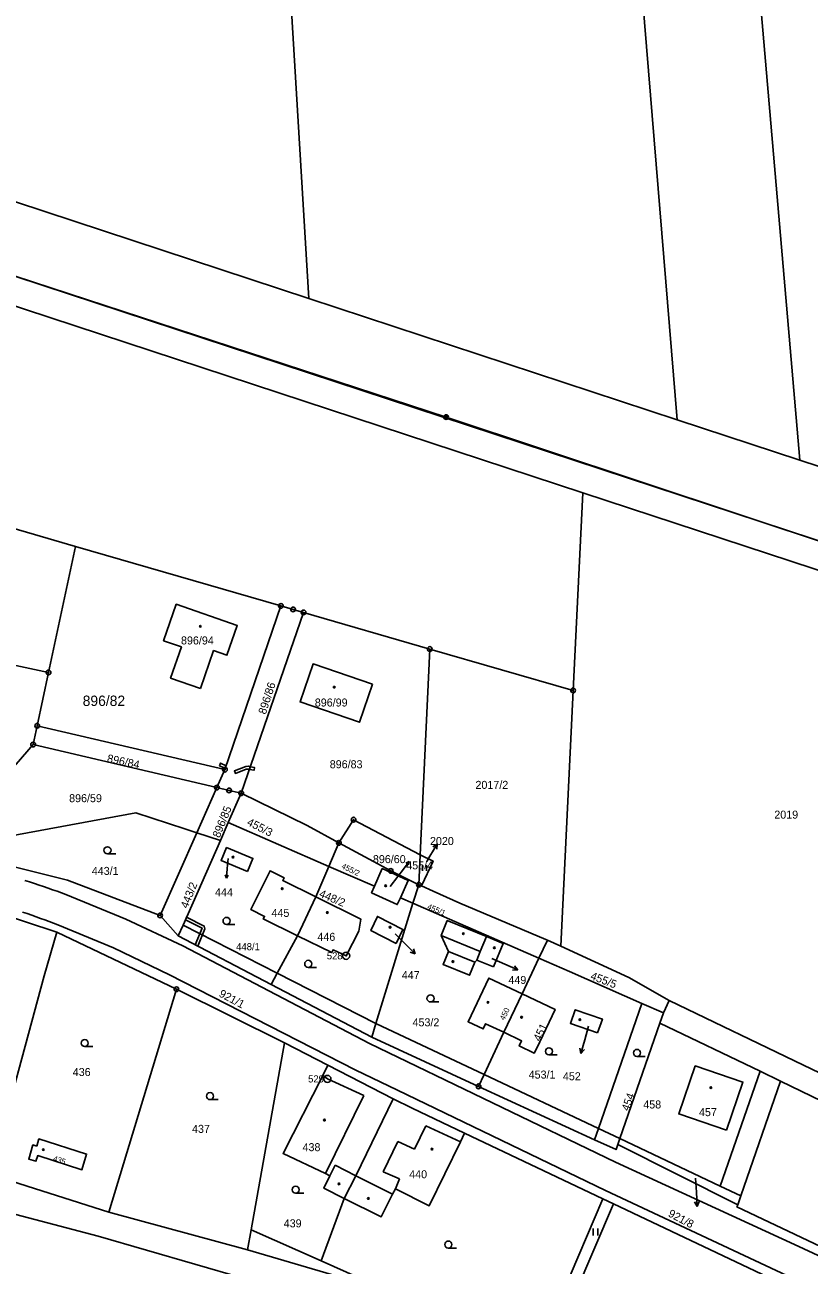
# Model space of a CAD drawing. Extents: x -504988 to -494607, y -1123820 to -1114018.
# Drawn here: x -500256.5 to -500090, y -1121176.7 to -1120913.2 of the extents above; entities that cross this region are included whole.
import ezdxf

# ---------------------------------------------------------------- set-up
doc = ezdxf.new("R2010")
doc.units = 0
for name, color, linetype in [('Hranice parcel', 7, 'Continuous'), ('Parcelní čísla', 7, 'Continuous'), ('Pop  PČ popisy', 7, 'Continuous'), ('Poz předměty', 7, 'Continuous'), ('Vnitřní kresba', 7, 'Continuous'), ('Věcná břemena k části', 7, 'Continuous'), ('Značky bodu BP', 7, 'Continuous'), ('Značky budov', 7, 'Continuous'), ('Značky kultur', 7, 'Continuous')]:
    doc.layers.add(name, color=color, linetype=linetype)

msp = doc.modelspace()

# ---------------------------------------------------------------- linework, layer by layer
at = {"layer": 'Hranice parcel'}
for p, q in [((-500118.03, -1120997.12), (-500196.22, -1120971.37)), ((-500092.04, -1121005.67), (-500118.03, -1120997.12)), ((-500008.22, -1121033.27), (-500092.04, -1121005.67)), ((-500138.09, -1121012.62), (-500140.11, -1121054.59)), ((-500049.77, -1121041.7), (-500138.09, -1121012.62)), ((-500251.41, -1121050.77), (-500245.68, -1121024.01)), ((-500202.12, -1121036.64), (-500245.68, -1121024.01)), ((-500214, -1121071.42), (-500202.12, -1121036.64)), ((-500197.32, -1121038.04), (-500210.54, -1121076.42)), ((-500170.53, -1121045.8), (-500197.32, -1121038.04)), ((-500172.54, -1121089.48), (-500170.53, -1121045.8)), ((-500170.53, -1121045.8), (-500140.11, -1121054.59)), ((-500253.84, -1121062.1), (-500251.41, -1121050.77)), ((-500140.11, -1121054.59), (-500142.73, -1121108.92)), ((-500254.69, -1121066.09), (-500253.84, -1121062.1)), ((-500253.84, -1121062.1), (-500214, -1121071.42)), ((-500274.16, -1121088.23), (-500254.69, -1121066.09)), ((-500254.69, -1121066.09), (-500215.69, -1121075.21)), ((-500215.69, -1121075.21), (-500214, -1121071.42)), ((-500219.95, -1121084.8), (-500215.69, -1121075.21)), ((-500210.54, -1121076.42), (-500213.28, -1121082.64)), ((-500274.16, -1121088.23), (-500232.91, -1121080.57)), ((-500232.91, -1121080.57), (-500222.5, -1121083.97)), ((-500227.75, -1121102.36), (-500219.95, -1121084.8)), ((-500222.5, -1121083.97), (-500219.95, -1121084.8)), ((-500214.95, -1121086.43), (-500219.95, -1121084.8)), ((-500213.28, -1121082.64), (-500214.95, -1121086.43)), ((-500191.94, -1121091.97), (-500213.28, -1121082.64)), ((-500189.82, -1121086.96), (-500191.94, -1121091.97)), ((-500172.83, -1121095.85), (-500172.54, -1121089.48)), ((-500194.7, -1121098.46), (-500191.94, -1121091.97)), ((-500182.29, -1121096.19), (-500191.94, -1121091.97)), ((-500172.83, -1121095.85), (-500174.14, -1121099.75)), ((-500172.28, -1121096.1), (-500172.83, -1121095.85)), ((-500198.61, -1121106.68), (-500194.7, -1121098.46)), ((-500174.14, -1121099.75), (-500176.76, -1121098.61)), ((-500174.14, -1121099.75), (-500147.38, -1121111.46)), ((-500223.9, -1121106.74), (-500227.75, -1121102.36)), ((-500224.28, -1121118.06), (-500249.64, -1121105.96)), ((-500223.9, -1121106.74), (-500204.22, -1121117.03)), ((-500147.38, -1121111.46), (-500145.57, -1121107.61)), ((-500142.73, -1121108.92), (-500145.57, -1121107.61)), ((-500147.38, -1121111.46), (-500150.93, -1121119.02)), ((-500238.67, -1121165.42), (-500224.28, -1121118.06)), ((-500201.34, -1121129.44), (-500224.28, -1121118.06)), ((-500204.22, -1121117.03), (-500182.85, -1121128.21)), ((-500154.85, -1121127.2), (-500150.93, -1121119.02)), ((-500120.95, -1121123.09), (-500125.53, -1121121.08)), ((-500119.71, -1121120.47), (-500120.95, -1121123.09)), ((-500121.69, -1121125.22), (-500120.95, -1121123.09)), ((-500130.2, -1121149.75), (-500121.69, -1121125.22)), ((-500121.69, -1121125.22), (-500100.44, -1121135.48)), ((-500208.44, -1121169.13), (-500201.34, -1121129.44)), ((-500192.14, -1121134.17), (-500201.34, -1121129.44)), ((-500182.85, -1121128.21), (-500160.18, -1121138.67)), ((-500154.85, -1121127.2), (-500159.01, -1121136.17)), ((-500178.28, -1121141.29), (-500192.14, -1121134.17)), ((-500159.01, -1121136.17), (-500160.18, -1121138.67)), ((-500108.92, -1121159.84), (-500100.44, -1121135.48)), ((-500160.18, -1121138.67), (-500135.55, -1121150.02)), ((-500133.8, -1121162.56), (-500163.15, -1121148.6)), ((-500130.64, -1121151.02), (-500130.2, -1121149.75)), ((-500130.2, -1121149.75), (-500108.92, -1121159.84)), ((-500105.2, -1121163.81), (-500130.64, -1121151.02)), ((-500263.78, -1121157.36), (-500238.67, -1121165.42)), ((-500193.58, -1121175.73), (-500188.67, -1121162.48)), ((-500133.8, -1121162.56), (-500146.46, -1121192.11)), ((-500144.15, -1121193.06), (-500131.54, -1121163.63)), ((-500131.54, -1121163.63), (-500133.8, -1121162.56)), ((-500238.67, -1121165.42), (-500209.2, -1121173.36)), ((-500209.2, -1121173.36), (-500208.44, -1121169.13)), ((-500208.44, -1121169.13), (-500193.58, -1121175.73)), ((-500193.58, -1121175.73), (-500148.1, -1121195.96))]:
    msp.add_line(p, q, dxfattribs=at)
for points in [[(-500092.04, -1121005.67), (-500107.28, -1120827.92), (-500122.52, -1120650.17), (-500137.76, -1120472.41), (-500153, -1120294.66)], [(-500118.03, -1120997.12), (-500132.29, -1120823.84), (-500146.54, -1120650.56), (-500160.8, -1120477.27), (-500175.05, -1120303.99)], [(-500196.22, -1120971.37), (-500205.99, -1120809.21), (-500215.76, -1120647.04), (-500225.53, -1120484.88), (-500235.3, -1120322.71)], [(-500764.98, -1120898.32), (-500631.41, -1120885.98), (-500618.26, -1120885.7), (-500608.56, -1120886.58), (-500597.08, -1120888.85), (-500587.15, -1120891.94), (-500532.37, -1120912.08), (-500524.35, -1120914.64), (-500516.15, -1120916.5), (-500513.53, -1120917), (-500396.19, -1120938.19), (-500282.34, -1120959.31), (-500275.43, -1120961.08), (-500094.63, -1121020.61), (-499913.83, -1121080.14), (-499909.87, -1121081.53), (-499905.97, -1121083.08), (-499793.8, -1121130.28), (-499791.45, -1121131.2), (-499789.49, -1121131.83)], [(-500481.13, -1120928.92), (-500397.25, -1120944.09), (-500283.44, -1120965.21), (-500278.08, -1120966.53), (-500138.09, -1121012.62)], [(-500196.22, -1120971.37), (-500270.98, -1120946.75), (-500275.13, -1120945.54)], [(-500245.68, -1121024.01), (-500266.58, -1121017.95), (-500317.57, -1121003.17)], [(-500219.19, -1121054.18), (-500225.54, -1121051.98), (-500223.24, -1121045.36), (-500227.01, -1121044.05), (-500224.32, -1121036.3), (-500211.38, -1121040.79), (-500213.58, -1121047.12), (-500216.4, -1121046.14), (-500219.19, -1121054.18)], [(-500197.32, -1121038.04), (-500199.55, -1121037.39), (-500202.12, -1121036.64)], [(-500251.41, -1121050.77), (-500303, -1121039.71), (-500307.92, -1121062.62)], [(-500182.71, -1121053.27), (-500185.48, -1121061.36), (-500198.06, -1121057.04), (-500195.29, -1121048.96), (-500182.71, -1121053.27)], [(-500210.54, -1121076.42), (-500213.12, -1121075.82), (-500215.69, -1121075.21)], [(-500189.82, -1121086.96), (-500196.54, -1121083.3), (-500210.54, -1121076.42)], [(-500172.54, -1121089.48), (-500186.7, -1121082.04), (-500189.82, -1121086.96)], [(-500214.95, -1121086.43), (-500222.89, -1121104.46), (-500223.9, -1121106.74)], [(-500172.83, -1121095.85), (-500178.82, -1121092.93), (-500189.82, -1121086.96)], [(-500227.75, -1121102.36), (-500247.44, -1121094.86), (-500274.16, -1121088.23)], [(-500209.24, -1121093.08), (-500208.07, -1121090.28), (-500213.66, -1121087.95), (-500214.82, -1121090.74), (-500209.24, -1121093.08)], [(-500172.28, -1121096.1), (-500169.84, -1121090.82), (-500172.54, -1121089.48)], [(-500182.29, -1121096.19), (-500180.63, -1121092.43), (-500175.09, -1121094.98), (-500176.76, -1121098.61)], [(-500194.7, -1121098.46), (-500201.74, -1121094.99), (-500201.44, -1121094.38), (-500204.43, -1121092.9), (-500208.49, -1121101.14), (-500205.6, -1121102.57), (-500205.86, -1121103.11), (-500198.61, -1121106.68)], [(-500176.76, -1121098.61), (-500177.44, -1121100.08), (-500182.9, -1121097.57), (-500182.29, -1121096.19)], [(-500145.57, -1121107.61), (-500145.9, -1121107.46), (-500164.17, -1121099.76), (-500169.8, -1121097.22), (-500172.28, -1121096.1)], [(-500249.64, -1121105.96), (-500263.05, -1121101.54), (-500276.26, -1121098.57)], [(-500198.61, -1121106.68), (-500191.33, -1121110.27), (-500191.05, -1121109.68), (-500188.28, -1121110.95), (-500185.58, -1121105.72), (-500185.19, -1121103.14), (-500194.7, -1121098.46)], [(-500182.85, -1121128.21), (-500181.97, -1121125.34), (-500174.14, -1121099.75)], [(-500177.69, -1121108.31), (-500176.22, -1121105.34), (-500181.66, -1121102.6), (-500183.07, -1121105.55), (-500177.69, -1121108.31)], [(-500263.78, -1121157.36), (-500252.33, -1121115.17), (-500249.64, -1121105.96)], [(-500157.01, -1121113.32), (-500154.96, -1121108.33), (-500158.52, -1121106.87), (-500166.82, -1121103.47), (-500168.11, -1121106.61), (-500166.58, -1121110.03), (-500167.7, -1121112.81), (-500162.09, -1121115.08), (-500160.96, -1121112.3), (-500160.57, -1121111.86), (-500157.01, -1121113.32)], [(-500204.22, -1121117.03), (-500202.93, -1121114.65), (-500198.61, -1121106.68)], [(-500119.71, -1121120.47), (-500128.32, -1121115.57), (-500142.73, -1121108.92)], [(-500125.53, -1121121.08), (-500140.91, -1121114.29), (-500147.38, -1121111.46)], [(-500150.93, -1121119.02), (-500157.99, -1121115.67), (-500162.39, -1121124.94), (-500159.18, -1121126.46), (-500158.68, -1121125.39), (-500154.85, -1121127.2)], [(-500154.85, -1121127.2), (-500151.04, -1121129.01), (-500151.55, -1121130.08), (-500148.36, -1121131.59), (-500147.84, -1121130.53), (-500143.96, -1121122.32), (-500150.93, -1121119.02)], [(-500125.53, -1121121.08), (-500134.72, -1121147.62), (-500135.55, -1121150.02)], [(-500047.43, -1121155.01), (-500063.25, -1121147.6), (-500091.2, -1121134.17), (-500119.71, -1121120.47)], [(-500093.53, -1121309.79), (-500096.64, -1121297.58), (-500125.14, -1121250.31), (-500143.37, -1121221.49), (-500154.49, -1121207.58), (-500171.25, -1121193.24), (-500179.79, -1121189.25), (-500191.69, -1121184.83), (-500210.15, -1121179.42), (-500240.92, -1121170.5), (-500265.19, -1121164.1), (-500289.32, -1121158.74), (-500305.17, -1121156.16), (-500321.82, -1121158.18), (-500359.14, -1121160.88), (-500369.12, -1121161.84), (-500376.67, -1121161), (-500384.33, -1121158.44), (-500393.5, -1121153.73), (-500419.45, -1121136.05), (-500446.85, -1121123.24)], [(-500134.92, -1121127.3), (-500133.91, -1121124.38), (-500139.68, -1121122.39), (-500140.69, -1121125.31), (-500134.92, -1121127.3)], [(-500192.14, -1121134.17), (-500193.26, -1121136.37), (-500201.67, -1121152.9), (-500192.67, -1121157.21), (-500191.73, -1121157.66), (-500193.04, -1121160.28), (-500188.67, -1121162.48)], [(-500107.55, -1121147.98), (-500104.08, -1121137.78), (-500114.22, -1121134.33), (-500117.69, -1121144.54), (-500107.55, -1121147.98)], [(-500100.44, -1121135.48), (-500096.12, -1121137.57), (-500065.25, -1121152.48)], [(-500188.67, -1121162.48), (-500186.19, -1121157.65), (-500178.28, -1121141.29)], [(-500163.15, -1121148.6), (-500174.3, -1121143.3), (-500178.28, -1121141.29)], [(-500253.93, -1121151.39), (-500254.75, -1121151.1), (-500255.63, -1121154.11), (-500254.11, -1121154.58), (-500253.73, -1121153.37), (-500244.35, -1121156.37), (-500243.36, -1121153.04), (-500253.47, -1121149.84), (-500253.93, -1121151.39)], [(-500188.67, -1121162.48), (-500180.85, -1121166.41), (-500178.41, -1121161.55), (-500177.84, -1121160.4), (-500170.64, -1121164.03), (-500164.05, -1121150.45), (-500163.15, -1121148.6)], [(-500135.55, -1121150.02), (-500131.02, -1121152.11), (-500130.64, -1121151.02)], [(-500108.92, -1121159.84), (-500104.54, -1121161.92), (-500105.2, -1121163.81)], [(-500131.54, -1121163.63), (-500071.42, -1121192.12), (-500041.43, -1121205.99), (-500018.61, -1121215)], [(-500105.2, -1121163.81), (-500105.36, -1121164.28), (-500073.93, -1121179.19)], [(-500150.54, -1121201.64), (-500168.18, -1121189.1), (-500177.87, -1121183.75), (-500190.18, -1121178.97), (-500209.2, -1121173.36)]]:
    msp.add_lwpolyline(points, dxfattribs=at)
at = {"layer": 'Pop  PČ popisy'}
for p, q in [((-500170.51, -1121089.79), (-500168.96, -1121087.22)), ((-500168.96, -1121087.22), (-500169.91, -1121087.82)), ((-500168.96, -1121087.22), (-500169.05, -1121088.33)), ((-500171.18, -1121090.89), (-500170.51, -1121089.79)), ((-500213.51, -1121092.38), (-500213.69, -1121094.47)), ((-500213.34, -1121090.29), (-500213.51, -1121092.38)), ((-500176.12, -1121092.52), (-500174.91, -1121090.91)), ((-500174.91, -1121090.91), (-500175.58, -1121091.25)), ((-500174.91, -1121090.91), (-500175.05, -1121091.65)), ((-500213.69, -1121094.47), (-500213.98, -1121093.74)), ((-500213.69, -1121094.47), (-500213.28, -1121093.8)), ((-500177.85, -1121106.26), (-500175.75, -1121108.4)), ((-500175.75, -1121108.4), (-500173.67, -1121110.56)), ((-500173.67, -1121110.56), (-500174.72, -1121110.19)), ((-500173.67, -1121110.56), (-500174, -1121109.49)), ((-500157.36, -1121111.51), (-500154.62, -1121112.74)), ((-500154.62, -1121112.74), (-500151.88, -1121113.96)), ((-500151.88, -1121113.96), (-500152.59, -1121113.1)), ((-500151.88, -1121113.96), (-500153, -1121114.01)), ((-500136.84, -1121125.91), (-500137.66, -1121128.79)), ((-500137.66, -1121128.79), (-500138.49, -1121131.68)), ((-500138.49, -1121131.68), (-500138.69, -1121130.57)), ((-500138.49, -1121131.68), (-500137.73, -1121130.85)), ((-500114.13, -1121158.18), (-500113.96, -1121161.17)), ((-500113.96, -1121161.17), (-500113.8, -1121164.17)), ((-500113.8, -1121164.17), (-500114.35, -1121163.19)), ((-500113.8, -1121164.17), (-500113.35, -1121163.14))]:
    msp.add_line(p, q, dxfattribs=at)
msp.add_lwpolyline([(-500178.93, -1121096.24), (-500177.34, -1121094.13), (-500176.12, -1121092.52)], dxfattribs=at)
at = {"layer": 'Poz předměty'}
for p, q in [((-500278.83, -1120959.96), (-500167.07, -1120996.54)), ((-500167.07, -1120996.54), (-500040.79, -1121038.52))]:
    msp.add_line(p, q, dxfattribs=at)
for radius in [0.5, 0.4, 0.3, 0.2, 0.1]:
    msp.add_circle((-500167.07, -1120996.54), radius, dxfattribs=at)
at = {"layer": 'Vnitřní kresba'}
for p, q in [((-500247.75, -1121097.91), (-500235.05, -1121103.16)), ((-500235.05, -1121103.16), (-500222.93, -1121108.85)), ((-500237.63, -1121109.26), (-500249.47, -1121104.35)), ((-500222.89, -1121104.46), (-500202.93, -1121114.65)), ((-500159.81, -1121110.01), (-500168.11, -1121106.61)), ((-500159.81, -1121110.01), (-500158.52, -1121106.87)), ((-500225.79, -1121114.98), (-500237.63, -1121109.26)), ((-500222.93, -1121108.85), (-500183.35, -1121129.56)), ((-500166.58, -1121110.03), (-500160.96, -1121112.3)), ((-500160.57, -1121111.86), (-500159.81, -1121110.01)), ((-500186.35, -1121135.17), (-500225.79, -1121114.98)), ((-500202.93, -1121114.65), (-500181.97, -1121125.34)), ((-500159.01, -1121136.17), (-500181.97, -1121125.34)), ((-500183.35, -1121129.56), (-500131.11, -1121154.78)), ((-500193.26, -1121136.37), (-500192.25, -1121137.09)), ((-500192.25, -1121137.09), (-500184.56, -1121140.61)), ((-500177.41, -1121139.49), (-500186.35, -1121135.17)), ((-500134.72, -1121147.62), (-500159.01, -1121136.17)), ((-500104.54, -1121161.92), (-500096.12, -1121137.57)), ((-500133.27, -1121160.81), (-500177.41, -1121139.49)), ((-500184.56, -1121140.61), (-500192.67, -1121157.21)), ((-500173.79, -1121152.03), (-500171.39, -1121147.09)), ((-500171.39, -1121147.09), (-500164.05, -1121150.45)), ((-500134.72, -1121147.62), (-500130.2, -1121149.75)), ((-500180.39, -1121156.81), (-500177.32, -1121150.41)), ((-500177.32, -1121150.41), (-500173.79, -1121152.03)), ((-500191.73, -1121157.66), (-500190.61, -1121155.43)), ((-500190.61, -1121155.43), (-500186.19, -1121157.65)), ((-500131.11, -1121154.78), (-500092.19, -1121172.69)), ((-500186.19, -1121157.65), (-500178.41, -1121161.55)), ((-500176.93, -1121158.31), (-500180.39, -1121156.81)), ((-500177.84, -1121160.4), (-500176.93, -1121158.31)), ((-500094.76, -1121178.83), (-500133.27, -1121160.81)), ((-500092.19, -1121172.69), (-500053.36, -1121190.75))]:
    msp.add_line(p, q, dxfattribs=at)
for points in [[(-500256.47, -1121094.94), (-500255.45, -1121095.27), (-500254.44, -1121095.59), (-500253.45, -1121095.92), (-500252.48, -1121096.25), (-500251.51, -1121096.58), (-500250.57, -1121096.91), (-500249.63, -1121097.24), (-500248.68, -1121097.58), (-500247.75, -1121097.91)], [(-500249.47, -1121104.35), (-500250.37, -1121104.01), (-500251.28, -1121103.67), (-500252.19, -1121103.33), (-500253.1, -1121103), (-500254.04, -1121102.66), (-500254.98, -1121102.33), (-500255.94, -1121102), (-500256.92, -1121101.66)]]:
    msp.add_lwpolyline(points, dxfattribs=at)
at = {"layer": 'Věcná břemena k části'}
for points in [[(-500215.17, -1121070.59), (-500213.91, -1121071.16), (-500213.72, -1121070.59), (-500214.92, -1121070.04)], [(-500208.6, -1121070.79), (-500209.01, -1121070.71), (-500209.6, -1121070.74), (-500211.98, -1121071.67), (-500211.76, -1121072.23), (-500209.47, -1121071.33), (-500209.06, -1121071.31), (-500208.8, -1121071.36)], [(-500208.6, -1121070.79), (-500208.8, -1121071.36), (-500207.83, -1121071.56), (-500207.72, -1121070.97)], [(-500220.32, -1121108.61), (-500219.78, -1121108.89), (-500218.25, -1121105.21), (-500218.38, -1121104.62), (-500222.13, -1121102.74), (-500222.38, -1121103.29), (-500218.84, -1121105.06)]]:
    msp.add_lwpolyline(points, close=True, dxfattribs=at)
at = {"layer": 'Značky bodu BP'}
for centre, radius in [((-500202.12, -1121036.64), 0.5), ((-500202.12, -1121036.64), 0.0303), ((-500199.55, -1121037.39), 0.5), ((-500199.55, -1121037.39), 0.0303), ((-500197.32, -1121038.04), 0.5), ((-500197.32, -1121038.04), 0.0303), ((-500170.53, -1121045.8), 0.5), ((-500170.53, -1121045.8), 0.0303), ((-500251.41, -1121050.77), 0.5), ((-500251.41, -1121050.77), 0.0303), ((-500140.11, -1121054.59), 0.5), ((-500140.11, -1121054.59), 0.0303), ((-500253.84, -1121062.1), 0.5), ((-500253.84, -1121062.1), 0.0303), ((-500254.69, -1121066.09), 0.5), ((-500254.69, -1121066.09), 0.0303), ((-500214, -1121071.42), 0.5), ((-500214, -1121071.42), 0.0303), ((-500215.69, -1121075.21), 0.5), ((-500215.69, -1121075.21), 0.0303), ((-500213.12, -1121075.82), 0.5), ((-500213.12, -1121075.82), 0.0303), ((-500210.54, -1121076.42), 0.5), ((-500210.54, -1121076.42), 0.0303), ((-500186.7, -1121082.04), 0.5), ((-500186.7, -1121082.04), 0.0303), ((-500189.82, -1121086.96), 0.5), ((-500189.82, -1121086.96), 0.0303), ((-500178.82, -1121092.93), 0.5), ((-500178.82, -1121092.93), 0.0303), ((-500172.83, -1121095.85), 0.5), ((-500172.83, -1121095.85), 0.0303), ((-500227.75, -1121102.36), 0.5), ((-500227.75, -1121102.36), 0.0303), ((-500188.28, -1121110.95), 0.75), ((-500188.28, -1121110.95), 0.03), ((-500224.28, -1121118.06), 0.5), ((-500224.28, -1121118.06), 0.0303), ((-500192.25, -1121137.09), 0.75), ((-500192.25, -1121137.09), 0.03), ((-500160.18, -1121138.67), 0.5), ((-500160.18, -1121138.67), 0.0303)]:
    msp.add_circle(centre, radius, dxfattribs=at)
at = {"layer": 'Značky budov'}
for centre in [(-500219.21, -1121040.98), (-500190.82, -1121053.9), (-500212.29, -1121090), (-500201.85, -1121096.7), (-500179.89, -1121096.08), (-500192.26, -1121101.76), (-500178.95, -1121104.88), (-500163.4, -1121106.26), (-500156.85, -1121109.24), (-500165.63, -1121112.17), (-500158.18, -1121120.83), (-500151.06, -1121123.99), (-500138.68, -1121124.51), (-500110.89, -1121138.95), (-500192.89, -1121145.84), (-500252.55, -1121152.1), (-500170.06, -1121152), (-500189.79, -1121159.39), (-500183.58, -1121162.47)]:
    msp.add_circle(centre, 0.175, dxfattribs=at)
at = {"layer": 'Značky kultur'}
for p, q in [((-500238.92, -1121089.29), (-500237.17, -1121089.29)), ((-500172.05, -1121092.92), (-500172.05, -1121091.72)), ((-500171.25, -1121092.92), (-500171.25, -1121091.72)), ((-500213.65, -1121104.29), (-500211.9, -1121104.29)), ((-500196.33, -1121113.41), (-500194.58, -1121113.41)), ((-500170.38, -1121120.75), (-500168.63, -1121120.75)), ((-500243.75, -1121130.23), (-500242, -1121130.23)), ((-500145.25, -1121131.99), (-500143.5, -1121131.99)), ((-500126.57, -1121132.32), (-500124.82, -1121132.32)), ((-500217.16, -1121141.49), (-500215.41, -1121141.49)), ((-500198.99, -1121161.37), (-500197.24, -1121161.37)), ((-500135.84, -1121170.37), (-500135.84, -1121168.87)), ((-500134.84, -1121170.37), (-500134.84, -1121168.87)), ((-500166.6, -1121173.02), (-500164.85, -1121173.02))]:
    msp.add_line(p, q, dxfattribs=at)
for centre in [(-500238.92, -1121088.54), (-500213.65, -1121103.54), (-500196.33, -1121112.66), (-500170.38, -1121120), (-500243.75, -1121129.48), (-500145.25, -1121131.24), (-500126.57, -1121131.57), (-500217.16, -1121140.74), (-500198.99, -1121160.62), (-500166.6, -1121172.27)]:
    msp.add_circle(centre, 0.75, dxfattribs=at)

# ---------------------------------------------------------------- texts
at = {"layer": 'Parcelní čísla'}
for s, height, p in [('896/94', 1.7, (-500223.32, -1121044.83)), ('896/82', 2.2, (-500244.18, -1121057.89)), ('896/99', 1.7, (-500194.93, -1121058.01)), ('896/83', 1.7, (-500191.76, -1121071.12)), ('2017/2', 1.7, (-500160.84, -1121075.5)), ('896/59', 1.7, (-500247.06, -1121078.33)), ('2019', 1.7, (-500097.43, -1121081.82)), ('2020', 1.7, (-500170.49, -1121087.42)), ('896/60', 1.7, (-500182.6, -1121091.27)), ('443/1', 1.7, (-500242.25, -1121093.77)), ('455/4', 1.7, (-500175.53, -1121092.59)), ('444', 1.7, (-500216.1, -1121098.29)), ('445', 1.7, (-500204.12, -1121102.68)), ('448/1', 1.5, (-500211.61, -1121109.76)), ('446', 1.7, (-500194.38, -1121107.77)), ('447', 1.7, (-500176.47, -1121115.89)), ('449', 1.7, (-500153.85, -1121116.93)), ('453/2', 1.7, (-500174.19, -1121125.92)), ('436', 1.7, (-500246.29, -1121136.48)), ('453/1', 1.7, (-500149.55, -1121137.02)), ('452', 1.7, (-500142.29, -1121137.38)), ('458', 1.7, (-500125.23, -1121143.37)), ('457', 1.7, (-500113.41, -1121145)), ('437', 1.7, (-500220.98, -1121148.55)), ('438', 1.7, (-500197.53, -1121152.44)), ('440', 1.7, (-500174.9, -1121158.19)), ('439', 1.7, (-500201.53, -1121168.61))]:
    msp.add_text(s, height=height, dxfattribs=at).set_placement(p)
for s, height, rotation, p in [('896/86', 1.7, 72, (-500205.36, -1121059.8)), ('896/84', 1.7, 348, (-500239.11, -1121069.79)), ('896/85', 1.7, 68, (-500215.14, -1121086.02)), ('455/3', 1.7, 333, (-500209.49, -1121083.1)), ('455/2', 1.2, 334, (-500189.38, -1121092.3)), ('443/2', 1.7, 68, (-500221.93, -1121101.02)), ('448/2', 1.7, 337, (-500194.16, -1121098.36)), ('455/1', 1.2, 337, (-500171.19, -1121100.95)), ('455/5', 1.7, 339, (-500136.59, -1121115.87)), ('921/1', 1.7, 332, (-500215.42, -1121119.5)), ('450', 1.2, 64, (-500154.7, -1121124.77)), ('451', 1.7, 64, (-500147.14, -1121129.26)), ('454', 1.7, 70, (-500128.33, -1121144.04)), ('435', 1.2, 342, (-500250.56, -1121154.49)), ('921/8', 1.7, 332, (-500120.11, -1121166.19))]:
    msp.add_text(s, height=height, rotation=rotation, dxfattribs=at).set_placement(p)
at = {"layer": 'Značky bodu BP'}
for s, p in [('528', (-500192.38, -1121111.7)), ('529', (-500196.35, -1121137.84))]:
    msp.add_text(s, height=1.5, dxfattribs=at).set_placement(p)

doc.saveas('drawing.dxf')
